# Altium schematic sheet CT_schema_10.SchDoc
size 147 x 119 mm
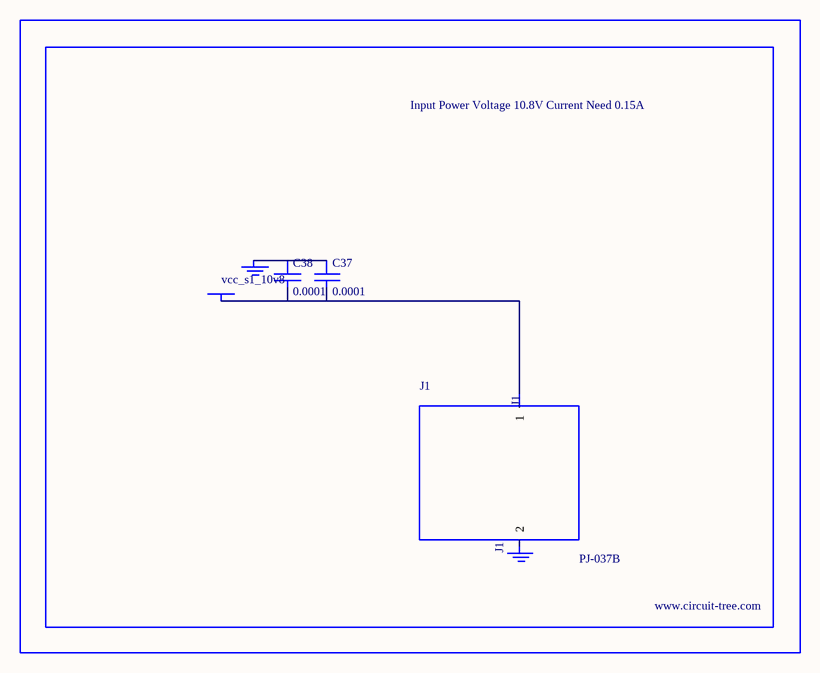
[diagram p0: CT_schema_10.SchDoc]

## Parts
BORDER9  (no value)
C37  0.0001  [EXV-9H]
C38  0.0001  [EXV-9H]
GND_INSTANCE_9_0  (no value)
GND_INSTANCE_9_1  (no value)
J1  PJ-037B  [PJ-037B_PACKAGE]
POWER_INSTANCE_9_0  vcc_s1_10v8

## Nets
NetC37_1: C37.1 C38.1 GND_INSTANCE_9_0.0(GND)
NetC37_2: C37.2 C38.2 J1.1 POWER_INSTANCE_9_0.0(PWR)

Not connected (* = marked no-connect by the designer): GND_INSTANCE_9_1 0(GND); J1 2

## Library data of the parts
BORDER9 = BORDER_PAGE9
C37 C38 = EDK107M035A9HAA
GND_INSTANCE_9_0 GND_INSTANCE_9_1 = GND
POWER_INSTANCE_9_0 = PWR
